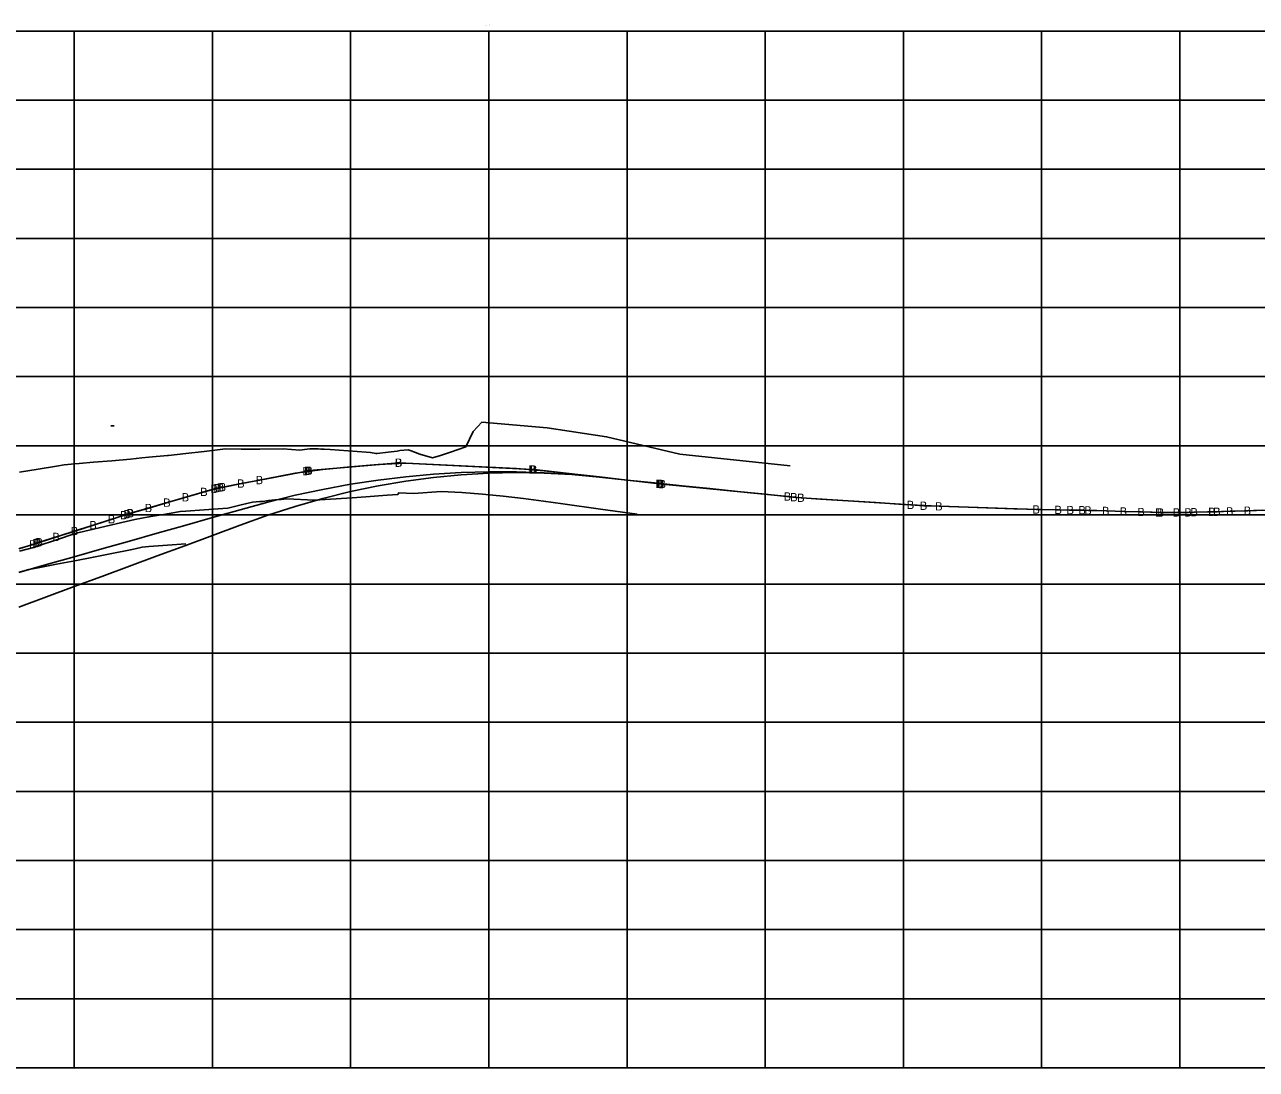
# Model space of a CAD drawing. Extents: x 76292 to 78417, y 50412 to 52585.
# Drawn here: x 77087.4 to 77533, y 50411.8 to 50789.6 of the extents above; entities that cross this region are included whole.
import ezdxf

# ---------------------------------------------------------------- set-up
doc = ezdxf.new("R2010")
doc.units = 0
for name, color, linetype in [('1', 7, 'Continuous'), ('2', 7, 'Continuous'), ('38', 7, 'Continuous'), ('5', 7, 'Continuous'), ('63', 7, 'Continuous')]:
    doc.layers.add(name, color=color, linetype=linetype)

msp = doc.modelspace()

# ---------------------------------------------------------------- linework, layer by layer
at = {"layer": '1'}
for p, q in [((76305.34, 50412.34), (78205.34, 50412.34)), ((77105.34, 50412.34), (77105.34, 50412.34)), ((77155.34, 50412.34), (77155.34, 50412.34)), ((77205.34, 50412.34), (77205.34, 50412.34)), ((77255.34, 50412.34), (77255.34, 50412.34)), ((77305.34, 50412.34), (77305.34, 50412.34)), ((77355.34, 50412.34), (77355.34, 50412.34)), ((77405.34, 50412.34), (77405.34, 50412.34)), ((77455.34, 50412.34), (77455.34, 50412.34)), ((77505.34, 50412.34), (77505.34, 50412.34))]:
    msp.add_line(p, q, dxfattribs=at)
for points in [[(77085.57, 50627.83), (77092.26, 50628.88), (77098.94, 50629.97), (77101.7, 50630.44), (77105.63, 50630.82), (77107.2, 50630.98), (77112.31, 50631.38), (77119, 50631.94), (77125.68, 50632.55), (77129.76, 50632.95), (77132.37, 50633.17), (77139.05, 50633.8), (77139.45, 50633.84), (77145.74, 50634.52), (77152.42, 50635.29), (77159.11, 50636.09), (77160.05, 50636.21), (77165.8, 50636.15), (77166.08, 50636.15), (77172.48, 50636.17), (77180.92, 50636.21), (77187.01, 50635.8), (77188.63, 50636.01), (77190.64, 50636.19), (77191.38, 50636.2), (77192.31, 50636.22), (77192.89, 50636.21), (77193.6, 50636.2), (77194.53, 50636.16), (77195.82, 50636.08), (77197.99, 50635.93), (77211, 50635.06), (77212.59, 50634.85), (77214.43, 50634.57), (77214.91, 50634.49), (77218.94, 50634.99), (77222.21, 50635.42), (77223.2, 50635.61), (77226.13, 50635.9), (77227.2, 50635.46), (77230.41, 50634.34), (77234.95, 50632.95), (77237.87, 50633.77), (77241.51, 50635.02), (77247.07, 50636.97), (77249.68, 50642.5), (77252.84, 50645.88), (77276.5, 50643.81), (77297.95, 50640.6), (77324.5, 50634.31), (77364.31, 50630.04)], [(77118.61, 50644.54), (77119.27, 50644.55), (77119.33, 50644.56), (77119.78, 50644.59)], [(77085.57, 50599.24), (77090.68, 50600.59), (77092.26, 50601.15), (77098.94, 50603.36), (77105.74, 50605.57), (77105.63, 50605.58), (77112.31, 50607.14), (77119, 50608.71), (77125.68, 50610.3), (77127.31, 50610.68), (77132.37, 50611.58), (77139.05, 50612.78), (77143.71, 50613.6), (77145.74, 50613.74), (77152.42, 50614.21), (77159.11, 50614.69), (77160.94, 50614.83), (77165.8, 50615.97), (77169.84, 50616.91), (77172.48, 50617.15), (77173.57, 50617.24), (77175.68, 50617.53), (77177.92, 50617.76), (77180.21, 50617.95), (77182.32, 50618.11), (77192.25, 50617.65), (77205.85, 50618.53), (77210.85, 50618.88), (77218.56, 50619.43), (77220.45, 50619.55), (77222.42, 50619.66), (77222.75, 50620.3), (77228.15, 50620.12), (77238.07, 50620.82), (77245.61, 50620.42), (77253.08, 50619.87), (77260.51, 50619.14), (77267.87, 50618.28), (77275.08, 50617.32), (77282.14, 50616.33), (77295.78, 50614.38), (77308.96, 50612.65)], [(77085.57, 50591.66), (77087.66, 50592.22), (77088.88, 50592.56), (77092.26, 50593.23), (77098.94, 50594.5), (77105.63, 50595.78), (77112.31, 50597.09), (77119, 50598.4), (77125.68, 50599.74), (77127.38, 50600.07), (77129.9, 50600.69), (77132.37, 50600.89), (77139.05, 50601.4), (77145.74, 50601.91)]]:
    msp.add_lwpolyline(points, dxfattribs=at)
at = {"layer": '2'}
msp.add_lwpolyline([(77085.57, 50600.13), (77090.54, 50601.69), (77091.7, 50602.07), (77092.26, 50602.25), (77092.85, 50602.44), (77098.94, 50604.37), (77105.63, 50606.5), (77112.31, 50608.64), (77119, 50610.78), (77123.49, 50612.22), (77124.68, 50612.6), (77125.68, 50612.9), (77125.89, 50612.96), (77132.37, 50614.83), (77139.05, 50616.77), (77145.74, 50618.71), (77152.42, 50620.65), (77156.12, 50621.73), (77157.26, 50622.03), (77158.37, 50622.25), (77159.11, 50622.39), (77165.8, 50623.67), (77172.48, 50624.94), (77189.46, 50628.19), (77189.96, 50628.28), (77190.43, 50628.34), (77222.76, 50631.22), (77222.83, 50631.23), (77222.87, 50631.22), (77222.92, 50631.22), (77271.18, 50628.78), (77271.32, 50628.77), (77271.45, 50628.76), (77271.58, 50628.74), (77271.71, 50628.73), (77317.12, 50623.62), (77317.38, 50623.59), (77317.65, 50623.56), (77318.23, 50623.49), (77363.52, 50619), (77365.87, 50618.75), (77368.4, 50618.54), (77408.06, 50615.95), (77412.78, 50615.65), (77418.32, 50615.44), (77453.52, 50614.31), (77461.49, 50614.14), (77465.85, 50614.09), (77470.15, 50614.04), (77472.26, 50613.97), (77478.67, 50613.77), (77485.07, 50613.58), (77491.48, 50613.39), (77497.89, 50613.21), (77498.48, 50613.2), (77504.3, 50613.23), (77508.48, 50613.25), (77510.7, 50613.3), (77517.11, 50613.43), (77518.9, 50613.47), (77523.52, 50613.63), (77529.92, 50613.86), (77536.33, 50614.1)], dxfattribs=at)
at = {"layer": '38'}
for points in [[(77085.34, 50600.05), (77095.34, 50603.23), (77105.34, 50606.41), (77115.34, 50609.61), (77125.34, 50612.79), (77135.34, 50615.69), (77145.34, 50618.59), (77155.34, 50621.5), (77165.34, 50623.58), (77175.34, 50625.49), (77185.34, 50627.4), (77195.34, 50628.78), (77205.34, 50629.67), (77215.34, 50630.56), (77225.34, 50631.1), (77235.34, 50630.59), (77245.34, 50630.09), (77255.34, 50629.58), (77265.34, 50629.08), (77275.34, 50628.32), (77285.34, 50627.2), (77295.34, 50626.07), (77305.34, 50624.95), (77315.34, 50623.82), (77325.34, 50622.79), (77335.34, 50621.79), (77345.34, 50620.8), (77355.34, 50619.81), (77365.34, 50618.81), (77375.34, 50618.08), (77385.34, 50617.43), (77395.34, 50616.78), (77405.34, 50616.13), (77415.34, 50615.56), (77425.34, 50615.22), (77435.34, 50614.89), (77445.34, 50614.57), (77455.34, 50614.27), (77465.34, 50614.1), (77475.34, 50613.87), (77485.34, 50613.57), (77495.34, 50613.28), (77505.34, 50613.23), (77515.34, 50613.39), (77525.34, 50613.7), (77535.34, 50614.07)], [(77085.34, 50600.05), (77095.34, 50603.23), (77105.34, 50606.41), (77115.34, 50609.61), (77125.34, 50612.79), (77135.34, 50615.69), (77145.34, 50618.59), (77155.34, 50621.5), (77165.34, 50623.58), (77175.34, 50625.49), (77185.34, 50627.4), (77195.34, 50628.78), (77205.34, 50629.67), (77215.34, 50630.56), (77225.34, 50631.1), (77235.34, 50630.59), (77245.34, 50630.09), (77255.34, 50629.58), (77265.34, 50629.08), (77275.34, 50628.32), (77285.34, 50627.2), (77295.34, 50626.07), (77305.34, 50624.95), (77315.34, 50623.82), (77325.34, 50622.79), (77335.34, 50621.79), (77345.34, 50620.8), (77355.34, 50619.81), (77365.34, 50618.81), (77375.34, 50618.08), (77385.34, 50617.43), (77395.34, 50616.78), (77405.34, 50616.13), (77415.34, 50615.56), (77425.34, 50615.22), (77435.34, 50614.89), (77445.34, 50614.57), (77455.34, 50614.27), (77465.34, 50614.1), (77475.34, 50613.87), (77485.34, 50613.57), (77495.34, 50613.28), (77505.34, 50613.23), (77515.34, 50613.39), (77525.34, 50613.7), (77535.34, 50614.07)], [(77085.34, 50591.54), (77095.34, 50594.38), (77105.34, 50597.22), (77115.34, 50600.05), (77125.34, 50602.89), (77135.34, 50605.73), (77145.34, 50608.56), (77155.34, 50611.4), (77165.34, 50614.23), (77175.34, 50616.98), (77185.34, 50619.43), (77195.34, 50621.57), (77205.34, 50623.4), (77215.34, 50624.93), (77225.34, 50626.14), (77235.34, 50627.04), (77245.34, 50627.64), (77255.34, 50627.92), (77265.34, 50627.89), (77275.34, 50627.56), (77285.34, 50626.92), (77295.34, 50625.97), (77305.34, 50624.94), (77315.34, 50623.91), (77325.34, 50622.88), (77335.34, 50621.85), (77345.34, 50620.82), (77355.34, 50619.79)], [(77085.34, 50578.99), (77095.34, 50582.69), (77105.34, 50586.39), (77115.34, 50590.09), (77125.34, 50593.8), (77135.34, 50597.5), (77145.34, 50601.2), (77155.34, 50604.9), (77165.34, 50608.6), (77175.34, 50612.2), (77185.34, 50615.43), (77195.34, 50618.28), (77205.34, 50620.75), (77215.34, 50622.84), (77225.34, 50624.56), (77235.34, 50625.9), (77245.34, 50626.85), (77255.34, 50627.43), (77265.34, 50627.63), (77275.34, 50627.45), (77285.34, 50626.9), (77295.34, 50625.97), (77305.34, 50624.94), (77315.34, 50623.91), (77325.34, 50622.88), (77335.34, 50621.85), (77345.34, 50620.82), (77355.34, 50619.79)]]:
    msp.add_lwpolyline(points, dxfattribs=at)
at = {"layer": '5'}
for p, q in [((77190.43, 50628.34), (77222.76, 50631.22)), ((77222.76, 50631.22), (77222.83, 50631.23)), ((77222.83, 50631.23), (77222.87, 50631.22)), ((77222.87, 50631.22), (77222.92, 50631.22)), ((77222.92, 50631.22), (77271.18, 50628.78)), ((77172.48, 50624.94), (77189.46, 50628.19)), ((77189.46, 50628.19), (77189.96, 50628.28)), ((77189.96, 50628.28), (77190.43, 50628.34)), ((77271.18, 50628.78), (77271.32, 50628.77)), ((77271.32, 50628.77), (77271.45, 50628.76)), ((77271.45, 50628.76), (77271.58, 50628.74)), ((77271.58, 50628.74), (77271.71, 50628.73)), ((77271.71, 50628.73), (77317.12, 50623.62)), ((77152.42, 50620.65), (77156.12, 50621.73)), ((77156.12, 50621.73), (77157.26, 50622.03)), ((77157.26, 50622.03), (77158.37, 50622.25)), ((77158.37, 50622.25), (77159.11, 50622.39)), ((77159.11, 50622.39), (77165.8, 50623.67)), ((77165.8, 50623.67), (77172.48, 50624.94)), ((77317.12, 50623.62), (77317.38, 50623.59)), ((77317.38, 50623.59), (77317.65, 50623.56)), ((77317.65, 50623.56), (77318.23, 50623.49)), ((77318.23, 50623.49), (77363.52, 50619)), ((77132.37, 50614.83), (77139.05, 50616.77)), ((77139.05, 50616.77), (77145.74, 50618.71)), ((77145.74, 50618.71), (77152.42, 50620.65)), ((77363.52, 50619), (77365.87, 50618.75)), ((77365.87, 50618.75), (77368.4, 50618.54)), ((77368.4, 50618.54), (77408.06, 50615.95)), ((77123.49, 50612.22), (77124.68, 50612.6)), ((77124.68, 50612.6), (77125.68, 50612.9)), ((77125.68, 50612.9), (77125.89, 50612.96)), ((77125.89, 50612.96), (77132.37, 50614.83)), ((77408.06, 50615.95), (77412.78, 50615.65)), ((77412.78, 50615.65), (77418.32, 50615.44)), ((77418.32, 50615.44), (77453.52, 50614.31)), ((77453.52, 50614.31), (77461.49, 50614.14)), ((77461.49, 50614.14), (77465.85, 50614.09)), ((77465.85, 50614.09), (77470.15, 50614.04)), ((77470.15, 50614.04), (77472.26, 50613.97)), ((77472.26, 50613.97), (77478.67, 50613.77)), ((77478.67, 50613.77), (77485.07, 50613.58)), ((77485.07, 50613.58), (77491.48, 50613.39)), ((77491.48, 50613.39), (77497.89, 50613.21)), ((77497.89, 50613.21), (77498.48, 50613.2)), ((77498.48, 50613.2), (77504.3, 50613.23)), ((77504.3, 50613.23), (77508.48, 50613.25)), ((77508.48, 50613.25), (77510.7, 50613.3)), ((77510.7, 50613.3), (77517.11, 50613.43)), ((77517.11, 50613.43), (77518.9, 50613.47)), ((77518.9, 50613.47), (77523.52, 50613.63)), ((77523.52, 50613.63), (77529.92, 50613.86)), ((77529.92, 50613.86), (77536.33, 50614.1)), ((77105.63, 50606.5), (77112.31, 50608.64)), ((77112.31, 50608.64), (77119, 50610.78)), ((77119, 50610.78), (77123.49, 50612.22)), ((77092.85, 50602.44), (77098.94, 50604.37)), ((77098.94, 50604.37), (77105.63, 50606.5)), ((77085.57, 50600.13), (77090.54, 50601.69)), ((77090.54, 50601.69), (77091.7, 50602.07)), ((77091.7, 50602.07), (77092.26, 50602.25)), ((77092.26, 50602.25), (77092.85, 50602.44))]:
    msp.add_line(p, q, dxfattribs=at)
at = {"layer": '63'}
for p, q in [((76305.34, 50787.34), (78205.34, 50787.34)), ((76305.34, 50787.34), (78205.34, 50787.34)), ((77105.34, 50412.34), (77105.34, 50787.34)), ((77155.34, 50412.34), (77155.34, 50787.34)), ((77205.34, 50412.34), (77205.34, 50787.34)), ((77255.34, 50412.34), (77255.34, 50787.34)), ((77305.34, 50412.34), (77305.34, 50787.34)), ((77355.34, 50412.34), (77355.34, 50787.34)), ((77405.34, 50412.34), (77405.34, 50787.34)), ((77455.34, 50412.34), (77455.34, 50787.34)), ((77505.34, 50412.34), (77505.34, 50787.34)), ((76305.34, 50762.34), (78205.34, 50762.34)), ((76305.34, 50737.34), (78205.34, 50737.34)), ((76305.34, 50712.34), (78205.34, 50712.34)), ((76305.34, 50687.34), (78205.34, 50687.34)), ((76305.34, 50662.34), (78205.34, 50662.34)), ((76305.34, 50637.34), (78205.34, 50637.34)), ((76305.34, 50612.34), (78205.34, 50612.34)), ((76305.34, 50587.34), (78205.34, 50587.34)), ((76305.34, 50562.34), (78205.34, 50562.34)), ((76305.34, 50537.34), (78205.34, 50537.34)), ((76305.34, 50512.34), (78205.34, 50512.34)), ((76305.34, 50487.34), (78205.34, 50487.34)), ((76305.34, 50462.34), (78205.34, 50462.34)), ((76305.34, 50437.34), (78205.34, 50437.34))]:
    msp.add_line(p, q, dxfattribs=at)

# ---------------------------------------------------------------- texts
at = {"layer": '1'}
msp.add_text('Exis_CL', height=0.36, dxfattribs=at).set_placement((77254.16, 50789.26))
for s, p in [('88', (77105.4, 50411.94)), ('+50', (77155.4, 50411.81)), ('89', (77205.4, 50411.94)), ('+50', (77255.4, 50411.81)), ('90', (77305.4, 50411.93)), ('+50', (77355.4, 50411.81)), ('91', (77405.4, 50411.96)), ('+50', (77455.4, 50411.81)), ('92', (77505.4, 50411.94))]:
    msp.add_text(s, height=0.12, rotation=90, dxfattribs=at).set_placement(p)
at = {"layer": '5'}
for p in [(77221.26, 50629.72), (77221.33, 50629.73), (77221.37, 50629.72), (77221.42, 50629.72), (77269.68, 50627.28), (77269.82, 50627.27), (77269.95, 50627.26), (77270.08, 50627.24), (77270.21, 50627.23), (77170.98, 50623.44), (77187.96, 50626.69), (77188.46, 50626.78), (77188.93, 50626.84), (77150.92, 50619.15), (77154.62, 50620.23), (77155.76, 50620.53), (77156.87, 50620.75), (77157.61, 50620.89), (77164.3, 50622.17), (77315.62, 50622.12), (77315.88, 50622.09), (77316.15, 50622.06), (77316.73, 50621.99), (77137.55, 50615.27), (77144.24, 50617.21), (77362.02, 50617.5), (77364.37, 50617.25), (77366.9, 50617.04), (77406.56, 50614.45), (77411.28, 50614.15), (77416.82, 50613.94), (77117.5, 50609.28), (77121.99, 50610.72), (77123.18, 50611.1), (77124.18, 50611.4), (77124.39, 50611.46), (77130.87, 50613.33), (77452.02, 50612.81), (77459.99, 50612.64), (77464.35, 50612.59), (77468.65, 50612.54), (77470.76, 50612.47), (77477.17, 50612.27), (77483.57, 50612.08), (77489.98, 50611.89), (77496.39, 50611.71), (77496.98, 50611.7), (77502.8, 50611.73), (77506.98, 50611.75), (77509.2, 50611.8), (77515.61, 50611.93), (77517.4, 50611.97), (77522.02, 50612.13), (77528.42, 50612.36), (77104.13, 50605), (77110.81, 50607.14), (77090.2, 50600.57), (77090.76, 50600.75), (77091.35, 50600.94), (77097.44, 50602.87), (77089.04, 50600.19)]:
    msp.add_text('B', height=3, dxfattribs=at).set_placement(p)

doc.saveas('drawing.dxf')
